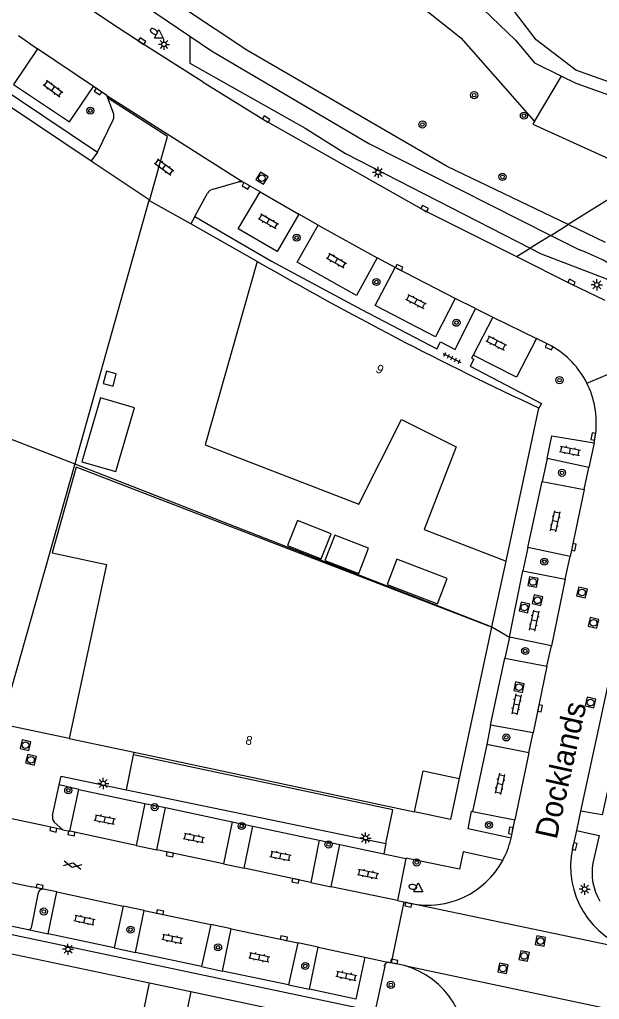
# Model space of a CAD drawing. Extents: x 131000 to 133013, y 393000 to 396501.
# Drawn here: x 131471.6 to 131536.8, y 393655.6 to 393765.9 of the extents above; entities that cross this region are included whole.
import ezdxf

# ---------------------------------------------------------------- set-up
doc = ezdxf.new("R2010")
doc.units = 0
for name, color, linetype in [('gg-afsc-hekwerk', 7, 'Continuous'), ('gg-anno-huisnummerreeks BGT', 7, 'Continuous'), ('gg-anno-openbare ruimte label', 7, 'Continuous'), ('gg-bbg-bijgebouw', 7, 'Continuous'), ('gg-bbg-hoofdgebouw', 7, 'Continuous'), ('gg-bbg-onder overbouw', 7, 'Continuous'), ('gg-bbg-overig bouwwerk', 7, 'Continuous'), ('gg-bbg-pand overbouw', 7, 'Continuous'), ('gg-knt-BGT kruinlijn', 7, 'Continuous'), ('gg-knt-onverhard', 7, 'Continuous'), ('gg-knt-verharding', 7, 'Continuous'), ('gg-knt-verharding nz', 7, 'Continuous'), ('gg-kntw-bovenkant insteek waterloop', 7, 'Continuous'), ('gg-kwrk-keermuur', 7, 'Continuous'), ('gt-grn-groengrens', 7, 'Continuous'), ('gt-grn-vlakafsluiter', 7, 'Continuous'), ('gt-grn-weggrens', 7, 'Continuous'), ('gt-symb-boom', 7, 'Continuous'), ('gt-symb-brandkraan', 7, 'Continuous'), ('gt-symb-gesloten verharding', 7, 'Continuous'), ('gt-symb-klinker verharding', 7, 'Continuous'), ('gt-symb-kolk', 7, 'Continuous'), ('gt-symb-lichtmast', 7, 'Continuous'), ('gt-symb-rioolschacht', 7, 'Continuous'), ('gt-symb-tegel verharding', 7, 'Continuous'), ('gt-symb-waterafsluiter', 7, 'Continuous')]:
    doc.layers.add(name, color=color, linetype=linetype)

# ---------------------------------------------------------------- blocks, each defined once
blk = doc.blocks.new('gt0-KL1')
at = {"layer": 'gt-symb-klinker verharding'}
for p, q in [((-1.15, 0.3), (1.15, 0.3)), ((-1, -0.3), (-1, 0.3)), ((-0.5, 0.3), (-0.5, 0.45)), ((0, -0.3), (0, 0.3)), ((0.5, 0.3), (0.5, 0.45)), ((1, -0.3), (1, 0.3)), ((-1.15, -0.3), (1.15, -0.3)), ((-0.5, -0.45), (-0.5, -0.3)), ((0.5, -0.45), (0.5, -0.3))]:
    blk.add_line(p, q, dxfattribs=at)
blk = doc.blocks.new('gt0-BOOM')
at = {"layer": 'gt-symb-boom'}
for radius in [0.4, 0.2]:
    blk.add_circle((0, 0), radius, dxfattribs=at)
blk = doc.blocks.new('gt0-KOLK')
at = {"layer": 'gt-symb-kolk'}
blk.add_lwpolyline([(0, 0), (0.37, 0), (0.37, 0.4), (-0.38, 0.4), (-0.38, 0), (0, 0)], dxfattribs=at)
blk = doc.blocks.new('gt0-LMAST')
at = {"layer": 'gt-symb-lichtmast'}
for p, q in [((-0.18, 0.17), (-0.45, 0.44)), ((-0.01, 0.25), (-0.01, 0.62)), ((0.17, 0.17), (0.44, 0.44)), ((-0.26, 0), (-0.63, 0)), ((-0.18, -0.18), (-0.45, -0.45)), ((-0.01, -0.25), (-0.01, -0.63)), ((0.44, -0.45), (0.17, -0.18)), ((0.24, 0), (0.62, 0))]:
    blk.add_line(p, q, dxfattribs=at)
blk.add_circle((-0.01, 0), 0.25, dxfattribs=at)
blk = doc.blocks.new('gt0-WAFSL')
at = {"layer": 'gt-symb-waterafsluiter'}
for p, q in [((-0.5, -0.33), (0, 0.67)), ((0, 0.67), (0.5, -0.33)), ((0.5, -0.33), (-0.5, -0.33))]:
    blk.add_line(p, q, dxfattribs=at)
blk = doc.blocks.new('gt0-BR')
at = {"layer": 'gt-symb-brandkraan'}
for centre, radius, start, end in [((-0.24, 0), 0.206, 107.5669, 252.4331), ((0.6, -2.66), 3, 106.892, 107.5669), ((0, -0.69), 0.938, 73.108, 106.892), ((-0.6, -2.66), 3, 72.4331, 73.108), ((0.24, 0), 0.206, 287.567, 72.4331), ((0.6, 2.66), 3, 252.4331, 253.108), ((0, 0.69), 0.938, 253.108, 286.8921), ((-0.6, 2.66), 3, 286.8921, 287.567)]:
    blk.add_arc(centre, radius, start, end, dxfattribs=at)
blk = doc.blocks.new('gt0-RS')
at = {"layer": 'gt-symb-rioolschacht'}
blk.add_lwpolyline([(-0.5, -0.5), (0.5, -0.5), (0.5, 0.5), (-0.5, 0.5)], close=True, dxfattribs=at)
blk.add_circle((0, 0), 0.375, dxfattribs=at)
blk = doc.blocks.new('gt0-TEG1')
at = {"layer": 'gt-symb-tegel verharding'}
for p, q in [((-1.12, 0), (1.12, 0)), ((-0.9, -0.25), (-0.9, 0.25)), ((-0.45, -0.25), (-0.45, 0.25)), ((0, -0.25), (0, 0.25)), ((0.45, -0.25), (0.45, 0.25)), ((0.9, -0.25), (0.9, 0.25))]:
    blk.add_line(p, q, dxfattribs=at)
blk = doc.blocks.new('gt0-GESVH1')
at = {"layer": 'gt-symb-gesloten verharding'}
for p, q in [((-0.99, -0.26), (0.01, 0.24)), ((0.01, -0.26), (-0.99, 0.24)), ((0.01, 0.24), (1.01, -0.26)), ((1.01, 0.24), (0.01, -0.26))]:
    blk.add_line(p, q, dxfattribs=at)

msp = doc.modelspace()

# ---------------------------------------------------------------- linework, layer by layer
at = {"layer": 'gg-afsc-hekwerk'}
for p, q in [((131486.19, 393745.5), (131486.14, 393745.52)), ((131490.83, 393742.89), (131486.19, 393745.5)), ((131498.3, 393738.68), (131490.83, 393742.89)), ((131477.8, 393715.91), (131469.54, 393686.63)), ((131477.8, 393715.91), (131524.69, 393697.58)), ((131524.69, 393697.58), (131526.29, 393704.95)), ((131524.64, 393697.51), (131524.69, 393697.58)), ((131477.16, 393685.01), (131469.54, 393686.63))]:
    msp.add_line(p, q, dxfattribs=at)
at = {"layer": 'gg-bbg-bijgebouw'}
for points in [[(131482.1, 393724.65), (131482.46, 393726.03), (131481.38, 393726.32), (131481.01, 393724.94), (131482.1, 393724.65)], [(131506.61, 393708.03), (131502.83, 393709.52), (131501.72, 393706.7), (131505.5, 393705.21), (131506.61, 393708.03)], [(131510.82, 393706.4), (131507.03, 393707.87), (131505.93, 393705.04), (131509.72, 393703.58), (131510.82, 393706.4)], [(131519.68, 393702.99), (131514.01, 393705.16), (131512.92, 393702.34), (131518.59, 393700.16), (131519.68, 393702.99)]]:
    msp.add_lwpolyline(points, dxfattribs=at)
at = {"layer": 'gg-bbg-hoofdgebouw'}
for p, q in [((131486.14, 393745.52), (131477.8, 393715.91)), ((131459.95, 393722.8), (131477.8, 393715.91)), ((131526.29, 393704.95), (131529.98, 393722.18)), ((131524.64, 393697.51), (131521.01, 393680.5)), ((131477.16, 393685.01), (131484.48, 393683.45)), ((131484.48, 393683.45), (131516, 393676.74)), ((131464.58, 393662.08), (131486.22, 393657.5)), ((131490.86, 393656.53), (131509.15, 393652.66))]:
    msp.add_line(p, q, dxfattribs=at)
for points in [[(131438.2, 393740.82), (131448.59, 393767.88), (131448.83, 393767.79), (131448.78, 393767.66), (131450.51, 393766.99), (131451.7, 393768.68), (131470.2, 393756.33), (131479.66, 393750)], [(131479.66, 393750), (131486.17, 393745.63), (131486.14, 393745.52)], [(131498.3, 393738.68), (131492.46, 393718.05), (131509.75, 393711.35), (131514.53, 393720.89), (131520.67, 393717.83), (131517.09, 393708.53), (131526.29, 393704.95)], [(131524.64, 393697.51), (131477.94, 393715.53), (131475.27, 393705.88), (131481.35, 393704.57), (131477.16, 393685.01)]]:
    msp.add_lwpolyline(points, dxfattribs=at)
msp.add_arc((131707.56, 394101.82), 419.12, 240.0476, 244.9331, dxfattribs=at)
at = {"layer": 'gg-bbg-onder overbouw'}
for points in [[(131516, 393676.74), (131516.98, 393681.35), (131521.01, 393680.5)], [(131490.86, 393656.53), (131490.24, 393653.6), (131485.61, 393654.58), (131486.22, 393657.5)]]:
    msp.add_lwpolyline(points, dxfattribs=at)
at = {"layer": 'gg-bbg-overig bouwwerk'}
msp.add_lwpolyline([(131478.61, 393716.12), (131482.43, 393715.04), (131484.51, 393722.21), (131480.7, 393723.32), (131478.61, 393716.12)], dxfattribs=at)
at = {"layer": 'gg-bbg-pand overbouw'}
msp.add_line((131486.22, 393657.5), (131490.86, 393656.53), dxfattribs=at)
msp.add_lwpolyline([(131521.01, 393680.5), (131520.03, 393675.89), (131516, 393676.74)], dxfattribs=at)
at = {"layer": 'gg-knt-BGT kruinlijn'}
for points in [[(131505.72, 393782.73), (131517.33, 393773.23), (131527.34, 393763.56), (131529.48, 393761.04), (131532.51, 393759.52)], [(131532.51, 393759.52), (131534.12, 393758.72), (131545.25, 393754.75)]]:
    msp.add_lwpolyline(points, dxfattribs=at)
at = {"layer": 'gg-knt-onverhard'}
for p, q in [((131472.05, 393776.8), (131490.73, 393764.04)), ((131537.47, 393740.82), (131533.26, 393742.83)), ((131531.3, 393741.61), (131534.53, 393739.98))]:
    msp.add_line(p, q, dxfattribs=at)
for points in [[(131533.26, 393742.83), (131519.66, 393749.35), (131497.14, 393762.43), (131475.77, 393776.65), (131473.76, 393778.1)], [(131490.73, 393764.04), (131493.16, 393762.39), (131510.85, 393751.96), (131531.3, 393741.61)], [(131546.91, 393726.9), (131546.89, 393721.28), (131542.81, 393702.16), (131537.07, 393676.41), (131534.66, 393676.81)], [(131534.19, 393674.64), (131536.76, 393674.09), (131536.04, 393670.97)]]:
    msp.add_lwpolyline(points, dxfattribs=at)
for centre, radius, start, end in [((131527.1, 393719.44), 21.84, 39.541, 70.1171), ((131542.28, 393669.9), 6.33, 170.3038, 210.1919)]:
    msp.add_arc(centre, radius, start, end, dxfattribs=at)
at = {"layer": 'gg-knt-verharding'}
for p, q in [((131471.49, 393764.09), (131473.62, 393762.58)), ((131479.92, 393758.36), (131473.62, 393762.58)), ((131481.4, 393757.36), (131479.92, 393758.36)), ((131481.52, 393757.04), (131481.4, 393757.36)), ((131481.4, 393757.36), (131496.82, 393747.56)), ((131482.15, 393755.37), (131481.52, 393757.04)), ((131480.35, 393750.99), (131482.11, 393754.61)), ((131493.35, 393746.82), (131496.22, 393747.63)), ((131498.65, 393746.49), (131496.82, 393747.56)), ((131491.29, 393743.72), (131492.74, 393746.34)), ((131498.65, 393746.49), (131503, 393743.98)), ((131505.16, 393742.77), (131503, 393743.98)), ((131505.16, 393742.77), (131511.81, 393739.07)), ((131513.82, 393738.01), (131511.81, 393739.07)), ((131520.56, 393734.51), (131513.82, 393738.01)), ((131522.84, 393733.38), (131520.56, 393734.51)), ((131520.7, 393729.06), (131522.84, 393733.38)), ((131522.84, 393733.38), (131524.81, 393732.41)), ((131524.81, 393732.41), (131522.57, 393728.13)), ((131524.81, 393732.41), (131529.69, 393730.01)), ((131531.44, 393729.13), (131529.69, 393730.01)), ((131536.17, 393718.26), (131536.36, 393719.36)), ((131536.17, 393718.26), (131535.6, 393715.49)), ((131535.6, 393715.49), (131530.9, 393716.52)), ((131535.08, 393713.01), (131535.6, 393715.49)), ((131528.74, 393706.5), (131530.33, 393713.93)), ((131530.33, 393713.93), (131535.08, 393713.01)), ((131535.08, 393713.01), (131533.49, 393705.49)), ((131533.49, 393705.49), (131528.74, 393706.5)), ((131532.93, 393702.94), (131533.49, 393705.49)), ((131526.67, 393696.41), (131528.17, 393703.88)), ((131528.17, 393703.88), (131532.93, 393702.94)), ((131532.93, 393702.94), (131531.38, 393695.43)), ((131531.38, 393695.43), (131526.67, 393696.41)), ((131530.88, 393693.13), (131531.38, 393695.43)), ((131524.53, 393686.5), (131526.14, 393694.05)), ((131526.14, 393694.05), (131530.88, 393693.13)), ((131530.88, 393693.13), (131529.33, 393685.64)), ((131529.33, 393685.64), (131524.53, 393686.5)), ((131528.86, 393683.37), (131529.33, 393685.64)), ((131524.12, 393684.31), (131522.52, 393676.8)), ((131528.86, 393683.37), (131524.12, 393684.31)), ((131528.86, 393683.37), (131527.28, 393675.86)), ((131476.05, 393679.79), (131476.27, 393680.75)), ((131476.27, 393680.75), (131483.61, 393679.23)), ((131475.3, 393676.34), (131476.05, 393679.79)), ((131478.26, 393679.28), (131476.05, 393679.79)), ((131477.24, 393674.57), (131478.26, 393679.28)), ((131478.26, 393679.28), (131485.66, 393677.67)), ((131483.61, 393679.23), (131512.78, 393673.18)), ((131474.43, 393675.16), (131459.12, 393678.4)), ((131485.66, 393677.67), (131484.72, 393672.98)), ((131485.66, 393677.67), (131488.01, 393677.24)), ((131487.03, 393672.49), (131488.01, 393677.24)), ((131488.01, 393677.24), (131495.48, 393675.61)), ((131522.52, 393676.8), (131527.28, 393675.86)), ((131534.66, 393676.81), (131534.19, 393674.64)), ((131476.46, 393674.73), (131475.49, 393675.6)), ((131495.48, 393675.61), (131494.52, 393670.91)), ((131495.48, 393675.61), (131497.81, 393675.14)), ((131496.85, 393670.4), (131497.81, 393675.14)), ((131497.81, 393675.14), (131505.26, 393673.55)), ((131526.85, 393673.79), (131527.28, 393675.86)), ((131476.46, 393674.73), (131477.24, 393674.57)), ((131484.72, 393672.98), (131477.24, 393674.57)), ((131534.19, 393674.64), (131533.76, 393672.67)), ((131484.72, 393672.98), (131487.03, 393672.49)), ((131505.26, 393673.55), (131504.34, 393668.8)), ((131505.26, 393673.55), (131507.58, 393673.06)), ((131506.62, 393668.33), (131507.58, 393673.06)), ((131507.58, 393673.06), (131512.54, 393672.03)), ((131512.78, 393673.18), (131512.54, 393672.03)), ((131526.82, 393673.63), (131526.85, 393673.79)), ((131494.52, 393670.91), (131487.03, 393672.49)), ((131512.54, 393672.03), (131515.02, 393671.51)), ((131494.52, 393670.91), (131496.85, 393670.4)), ((131515.02, 393671.51), (131514.09, 393666.78)), ((131504.34, 393668.8), (131496.85, 393670.4)), ((131468.81, 393669.21), (131472.97, 393668.33)), ((131504.34, 393668.8), (131506.62, 393668.33)), ((131474.3, 393668.05), (131472.97, 393668.33)), ((131475.78, 393667.73), (131474.3, 393668.05)), ((131474.81, 393663.01), (131475.78, 393667.73)), ((131475.78, 393667.73), (131483.26, 393666.14)), ((131514.09, 393666.78), (131506.62, 393668.33)), ((131514.09, 393666.78), (131514.79, 393666.62)), ((131514.79, 393666.62), (131515.56, 393666.44)), ((131483.26, 393666.14), (131482.24, 393661.43)), ((131485.59, 393665.66), (131483.26, 393666.14)), ((131484.61, 393660.92), (131485.59, 393665.66)), ((131485.59, 393665.66), (131493.08, 393664.06)), ((131472.57, 393663.5), (131474.81, 393663.01)), ((131482.24, 393661.43), (131474.81, 393663.01)), ((131493.08, 393664.06), (131492.05, 393659.35)), ((131495.38, 393663.58), (131493.08, 393664.06)), ((131494.42, 393658.84), (131495.38, 393663.58)), ((131495.38, 393663.58), (131502.88, 393662)), ((131502.88, 393662), (131501.84, 393657.3)), ((131505.18, 393661.51), (131502.88, 393662)), ((131482.24, 393661.43), (131484.61, 393660.92)), ((131492.05, 393659.35), (131484.61, 393660.92)), ((131504.2, 393656.78), (131505.18, 393661.51)), ((131505.18, 393661.51), (131510.42, 393660.39)), ((131510.42, 393660.39), (131509.41, 393655.66)), ((131510.42, 393660.39), (131513.14, 393659.81)), ((131513.37, 393659.76), (131513.14, 393659.81)), ((131514.85, 393659.45), (131513.37, 393659.76)), ((131492.05, 393659.35), (131494.42, 393658.84)), ((131501.84, 393657.3), (131494.42, 393658.84)), ((131501.84, 393657.3), (131504.2, 393656.78)), ((131509.41, 393655.66), (131504.2, 393656.78))]:
    msp.add_line(p, q, dxfattribs=at)
for points in [[(131492.24, 393758.84), (131485.26, 393763.27), (131481.8, 393765.54), (131478.37, 393767.85), (131472.46, 393771.99), (131466.22, 393776.51), (131460.77, 393780.57), (131455.05, 393785.02), (131453.1, 393786.57)], [(131454.45, 393776.01), (131450.94, 393770.72), (131480.35, 393750.99)], [(131473.62, 393762.58), (131470.91, 393758.6), (131477.2, 393754.38), (131479.92, 393758.36)], [(131492.24, 393758.84), (131499.21, 393754.52), (131517.03, 393744.45), (131527.45, 393739.22)], [(131503, 393743.98), (131500.57, 393739.81), (131496.17, 393742.34), (131498.65, 393746.49)], [(131491.29, 393743.72), (131499.93, 393738.69), (131510.05, 393733.27), (131518.51, 393728.84), (131518.92, 393729.64), (131520.55, 393728.78), (131520.7, 393729.06)], [(131511.81, 393739.07), (131509.47, 393734.85), (131502.81, 393738.58), (131505.16, 393742.77)], [(131527.45, 393739.22), (131533.56, 393736.16), (131537.37, 393734.32)], [(131520.56, 393734.51), (131518.36, 393730.21), (131511.56, 393733.71), (131513.82, 393738.01)], [(131529.69, 393730.01), (131527.47, 393725.67), (131522.57, 393728.13)], [(131522.57, 393728.13), (131522.4, 393727.81), (131522.67, 393727.67), (131522.25, 393726.88), (131530.25, 393722.69), (131529.98, 393722.18)], [(131544.22, 393721.46), (131536.87, 393687.03), (131534.66, 393676.81)], [(131530.9, 393716.52), (131531.43, 393719.07), (131536.17, 393718.26)], [(131526.85, 393673.79), (131522.01, 393674.83), (131522.4, 393676.82), (131522.52, 393676.8)], [(131525.91, 393671.28), (131521.48, 393672.25), (131521.05, 393670.3), (131515.02, 393671.53), (131515.02, 393671.51)], [(131472.57, 393663.5), (131472.79, 393663.54), (131472.88, 393663.63), (131472.92, 393663.71), (131473.73, 393667.67)], [(131468.41, 393664.67), (131468.46, 393664.47), (131468.55, 393664.36), (131468.63, 393664.32), (131472.57, 393663.5)], [(131511.65, 393654.59), (131512.68, 393659.38), (131512.55, 393659.41)]]:
    msp.add_lwpolyline(points, dxfattribs=at)
for centre, radius, start, end in [((131481.18, 393755.04), 1.03, 335.3611, 18.7483), ((131493.6, 393745.85), 0.999, 104.5476, 150.4281), ((131496.43, 393746.82), 0.833, 62.1923, 104.9396), ((131526.53, 393720.54), 9.89, 26.6826, 60.2694), ((131526.53, 393720.54), 9.9, 353.1519, 26.7154), ((131476.21, 393676.17), 0.926, 169.4841, 218.7325), ((131517.44, 393675.91), 9.65, 331.3112, 346.3266), ((131543.37, 393670.61), 9.83, 167.886, 254.7428), ((131517.44, 393675.91), 9.66, 258.7816, 331.3201), ((131474.21, 393667.57), 0.487, 78.7877, 168.0815), ((131513.09, 393659.26), 0.557, 84.8905, 164.2758), ((131512.37, 393650.45), 9.33, 348.5433, 74.5591)]:
    msp.add_arc(centre, radius, start, end, dxfattribs=at)
at = {"layer": 'gg-knt-verharding nz'}
for p, q in [((131480.35, 393750.99), (131479.66, 393750)), ((131491.29, 393743.72), (131490.83, 393742.89)), ((131476.46, 393674.73), (131474.43, 393675.16))]:
    msp.add_line(p, q, dxfattribs=at)
at = {"layer": 'gg-kntw-bovenkant insteek waterloop'}
msp.add_lwpolyline([(131548.3, 393755.14), (131534.13, 393760.18), (131529.65, 393763.6), (131525.78, 393768.76), (131519.26, 393774.49), (131507.56, 393784.11)], dxfattribs=at)
at = {"layer": 'gg-kwrk-keermuur'}
msp.add_line((131467.96, 393663.51), (131509.37, 393654.77), dxfattribs=at)
at = {"layer": 'gt-grn-groengrens'}
for p, q in [((131529.5, 393754.43), (131532.51, 393759.52)), ((131542.13, 393748.35), (131533.26, 393742.83)), ((131531.3, 393741.61), (131529.01, 393740.18)), ((131527.45, 393739.22), (131529.01, 393740.18)), ((131530.9, 393716.52), (131530.33, 393713.93)), ((131528.74, 393706.5), (131528.17, 393703.88)), ((131524.69, 393697.58), (131526.67, 393696.41)), ((131526.67, 393696.41), (131526.14, 393694.05)), ((131524.53, 393686.5), (131524.12, 393684.31))]:
    msp.add_line(p, q, dxfattribs=at)
for points in [[(131494.45, 393794.89), (131495.81, 393788.1), (131498.63, 393778.5), (131500.33, 393776.81), (131504.28, 393775.68), (131515.57, 393768.34), (131521.21, 393763.82), (131529.5, 393754.43)], [(131490.73, 393764.04), (131490.73, 393761), (131503.71, 393753.66), (131508.23, 393750.84), (131529.01, 393740.18)], [(131529.5, 393754.43), (131529.3, 393754.11), (131541.59, 393748.52)], [(131529.01, 393740.18), (131530.24, 393739.55), (131537.58, 393736.73), (131540.4, 393735.04), (131542.1, 393733.34), (131543.94, 393733.34)]]:
    msp.add_lwpolyline(points, dxfattribs=at)
at = {"layer": 'gt-grn-vlakafsluiter'}
for p, q in [((131483.61, 393679.23), (131484.42, 393683.15)), ((131484.42, 393683.15), (131484.48, 393683.45))]:
    msp.add_line(p, q, dxfattribs=at)
msp.add_lwpolyline([(131512.78, 393673.18), (131513.56, 393676.96), (131484.42, 393683.15)], dxfattribs=at)
at = {"layer": 'gt-grn-weggrens'}
for p, q in [((131531.3, 393741.61), (131533.26, 393742.83)), ((131535.37, 393724.99), (131543.12, 393728.23)), ((131514.79, 393666.62), (131513.37, 393659.76)), ((131540.78, 393661.13), (131515.56, 393666.44)), ((131514.85, 393659.45), (131539.08, 393654.32))]:
    msp.add_line(p, q, dxfattribs=at)
msp.add_lwpolyline([(131486.19, 393745.5), (131488.23, 393752.74), (131481.52, 393757.04)], dxfattribs=at)

# ---------------------------------------------------------------- block references
at = {"layer": 'gt-symb-boom'}
for p in [(131522.7, 393757.39), (131479.55, 393755.64), (131528.29, 393755.08), (131516.88, 393754.09), (131525.88, 393748.19), (131502.75, 393741.35), (131511.71, 393736.36), (131520.71, 393731.78), (131532.29, 393725.32), (131532.57, 393714.89), (131530.58, 393704.9), (131528.44, 393694.84), (131526.31, 393685.12), (131477.07, 393679.17), (131486.78, 393677.28), (131496.57, 393675.15), (131524.37, 393675.27), (131506.33, 393673.08), (131516.23, 393671.05), (131474.32, 393665.53), (131484.07, 393663.49), (131493.91, 393661.5), (131503.71, 393659.41), (131513.33, 393657.29)]:
    msp.add_blockref('gt0-BOOM', p, dxfattribs=at)
at = {"layer": 'gt-symb-brandkraan'}
for p, rotation in [((131486.7, 393764.55), 147.86710414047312), ((131515.8, 393668.31), 172.00768607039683)]:
    msp.add_blockref('gt0-BR', p, dxfattribs=dict(at, rotation=rotation))
at = {"layer": 'gt-symb-gesloten verharding', "rotation": -11.242525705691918}
msp.add_blockref('gt0-GESVH1', (131477.55, 393670.76), dxfattribs=at)
at = {"layer": 'gt-symb-klinker verharding'}
for p, rotation in [((131475.37, 393758.13), -36.423178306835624), ((131487.85, 393749.3), -36.423178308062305), ((131499.56, 393743.2), -30.05032329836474), ((131507.21, 393738.78), -30.07902586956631), ((131516.14, 393734.17), -27.38497058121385), ((131525.17, 393729.5), -27.33407585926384), ((131533.47, 393717.37), -11.71452521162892), ((131531.82, 393709.44), 78.04935273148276), ((131529.46, 393698.27), 78.04935273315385), ((131527.45, 393688.84), -101.77062600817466), ((131525.59, 393679.9), -101.71452521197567), ((131481.18, 393675.89), -11.71452521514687), ((131491.19, 393673.81), -11.714525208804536), ((131500.93, 393671.8), -11.658401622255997), ((131510.78, 393669.76), -11.714525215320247), ((131478.9, 393664.58), -12.062746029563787), ((131488.77, 393662.47), -12.06274602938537), ((131498.54, 393660.39), -12.006708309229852), ((131508.34, 393658.3), -12.062746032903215)]:
    msp.add_blockref('gt0-KL1', p, dxfattribs=dict(at, rotation=rotation))
at = {"layer": 'gt-symb-kolk'}
for p, rotation in [((131485.26, 393763.28), -32.95900987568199), ((131480.52, 393757.95), 145.67439803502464), ((131499.21, 393754.52), -32.13289585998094), ((131497.14, 393747.36), 150.0775130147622), ((131517.03, 393744.45), -29.46071361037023), ((131514.18, 393737.82), -26.10382498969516), ((131533.56, 393736.16), -26.616299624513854), ((131531.2, 393729.24), 155.0246653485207), ((131536.29, 393718.95), 79.85920685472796), ((131533.7, 393706.56), -102.06274602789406), ((131529.9, 393688.43), -101.82670392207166), ((131475.43, 393674.95), 168.0493527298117), ((131477.45, 393674.52), 171.00597824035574), ((131527.01, 393674.62), 82.06444963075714), ((131533.8, 393672.91), -104.17514205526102), ((131488.52, 393672.17), 168.11724113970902), ((131473.82, 393668.15), -12.062746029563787), ((131502.64, 393669.18), 167.3531465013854), ((131515.34, 393666.49), 166.99249520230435), ((131487.35, 393665.27), -12.29885516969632), ((131501.26, 393662.33), -12.006708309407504), ((131513.67, 393659.71), -12.29885516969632)]:
    msp.add_blockref('gt0-KOLK', p, dxfattribs=dict(at, rotation=rotation))
at = {"layer": 'gt-symb-lichtmast'}
for p in [(131487.84, 393763.1), (131511.9, 393748.7), (131536.49, 393736.05), (131481, 393679.94), (131510.5, 393673.8), (131535.13, 393668.05), (131477.05, 393661.28)]:
    msp.add_blockref('gt0-LMAST', p, dxfattribs=at)
at = {"layer": 'gt-symb-rioolschacht'}
for p, rotation in [((131498.84, 393748.05), 148.45632657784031), ((131529.31, 393702.61), -12.298855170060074), ((131534.82, 393701.42), -103.77214543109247), ((131529.83, 393700.55), 76.75619797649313), ((131528.34, 393699.75), -13.174926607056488), ((131536.13, 393698.01), -102.82712342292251), ((131527.74, 393690.77), -11.826703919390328), ((131535.79, 393689.04), -103.48012621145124), ((131472.27, 393684.26), 166.2971100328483), ((131472.88, 393682.61), 75.64421500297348), ((131530.15, 393662.21), 169.39794170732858), ((131528.32, 393660.53), 168.2293739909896), ((131525.94, 393659.14), 167.70114482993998)]:
    msp.add_blockref('gt0-RS', p, dxfattribs=dict(at, rotation=rotation))
at = {"layer": 'gt-symb-tegel verharding', "rotation": -26.66750216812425}
msp.add_blockref('gt0-TEG1', (131520.2, 393727.82), dxfattribs=at)
at = {"layer": 'gt-symb-waterafsluiter'}
for p in [(131487.25, 393764.12), (131516.41, 393668.08)]:
    msp.add_blockref('gt0-WAFSL', p, dxfattribs=at)

# ---------------------------------------------------------------- texts
at = {"layer": 'gg-anno-huisnummerreeks BGT'}
for s, rotation, p in [('9', 332.5, (131511.54, 393726.28)), ('8', 348, (131496.93, 393684.38))]:
    msp.add_text(s, height=1, rotation=rotation, dxfattribs=at).set_placement(p)
at = {"layer": 'gg-anno-openbare ruimte label'}
msp.add_text('Docklands', height=2.5, rotation=77.5, dxfattribs=at).set_placement((131531.96, 393673.57))

doc.saveas('drawing.dxf')
